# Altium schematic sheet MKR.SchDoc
size A4; Revision: V1.2; SheetNumber: 8; SheetTotal: 10
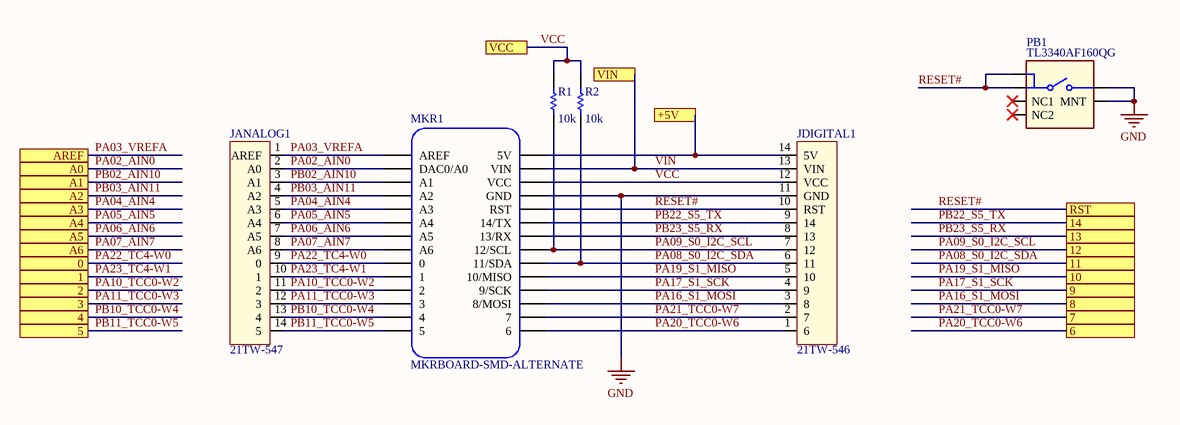
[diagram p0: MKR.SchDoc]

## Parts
JANALOG1  21TW-547  [21TW-332-Footprint-1]
JDIGITAL1  21TW-546  [21TW-331-Footprint-1]
MKR1  MKRBOARD-SMD-ALTERNATE  [MKRSHIELD]  (no BOM)
PB1  TL3340AF160QG  [TL3340AF160QG-Footprint-1]
R1  value 10k  [RES-0402]  (hidden comment: CRCW040210K0FKED)
R2  value 10k  [RES-0402]  (hidden comment: CRCW040210K0FKED)

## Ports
0, 1, 2, 3, 4, 5, 6, 7, 8, 9, 10, 11, 12, 13, 14, +5V, A0, A1, A2, A3, A4, A5, A6, AREF, RST, VCC, VIN

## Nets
GND: JDIGITAL1.11(GND) MKR1.GND PB1.2 PB1.MNT
+5V: JDIGITAL1.14(5V) MKR1.5V ; port +5V
PA02_AIN0: JANALOG1.2(A0) MKR1.A0(DAC0/A0) ; port A0
PA03_VREFA: JANALOG1.1(AREF) MKR1.AREF ; port AREF
PA04_AIN4: JANALOG1.5(A3) MKR1.A3 ; port A3
PA05_AIN5: JANALOG1.6(A4) MKR1.A4 ; port A4
PA06_AIN6: JANALOG1.7(A5) MKR1.A5 ; port A5
PA07_AIN7: JANALOG1.8(A6) MKR1.A6 ; port A6
PA08_S0_I2C_SDA: JDIGITAL1.6(11) MKR1.11(11/SDA) R2.1 ; port 11
PA09_S0_I2C_SCL: JDIGITAL1.7(12) MKR1.12(12/SCL) R1.1 ; port 12
PA10_TCC0-W2: JANALOG1.11(2) MKR1.2 ; port 2
PA11_TCC0-W3: JANALOG1.12(3) MKR1.3 ; port 3
PA16_S1_MOSI: JDIGITAL1.3(8) MKR1.8(8/MOSI) ; port 8
PA17_S1_SCK: JDIGITAL1.4(9) MKR1.9(9/SCK) ; port 9
PA19_S1_MISO: JDIGITAL1.5(10) MKR1.10(10/MISO) ; port 10
PA20_TCC0-W6: JDIGITAL1.1(6) MKR1.6 ; port 6
PA21_TCC0-W7: JDIGITAL1.2(7) MKR1.7 ; port 7
PA22_TC4-W0: JANALOG1.9(0) MKR1.0 ; port 0
PA23_TC4-W1: JANALOG1.10(1) MKR1.1 ; port 1
PB02_AIN10: JANALOG1.3(A1) MKR1.A1 ; port A1
PB03_AIN11: JANALOG1.4(A2) MKR1.A2 ; port A2
PB10_TCC0-W4: JANALOG1.13(4) MKR1.4 ; port 4
PB11_TCC0-W5: JANALOG1.14(5) MKR1.5 ; port 5
PB22_S5_TX: JDIGITAL1.9(14) MKR1.14(14/TX) ; port 14
PB23_S5_RX: JDIGITAL1.8(13) MKR1.13(13/RX) ; port 13
RESET#: JDIGITAL1.10(RST) MKR1.RST PB1.1 PB1.3 ; port RST
VCC: JDIGITAL1.12(VCC) MKR1.VCC R1.2 R2.2 ; port VCC
VIN: JDIGITAL1.13(VIN) MKR1.VIN ; port VIN

Not connected (* = marked no-connect by the designer): PB1 NC1* NC2*

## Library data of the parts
JANALOG1 = J0098-A.5: CONN STRIP SMD MKR F AREF; Manufacturer: 4UCON; Code Arduino: A5440; Number of Positions: 14
JDIGITAL1 = J0099-A.6: CONN STRIP SMD MKR F 5V; Manufacturer: 4UCON; Number of Positions: 14; Gender: Female; Code Arduino: A5441
MKR1 = UT0017-A.3: MKR board SMD pads alternate
PB1 = B0013-A.8: PUSHBUTTON SMD VERTICAL ANCHORS 4x3.4mm; Manufacturer: E-Switch; Code Arduino: B0013
R1 R2 = R0003-A.11: RES CHIP 0402 10K 1% 1/16W; Manufacturer: Vishay; Code Arduino: 0136; Power: 63mW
